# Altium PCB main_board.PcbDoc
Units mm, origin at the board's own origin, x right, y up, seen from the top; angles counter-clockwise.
Board outline 80.25 x 51.3 mm, 2 copper layers (Top Layer, Bottom Layer); 11 components, 14 nets, 56 pads, 87 vias.
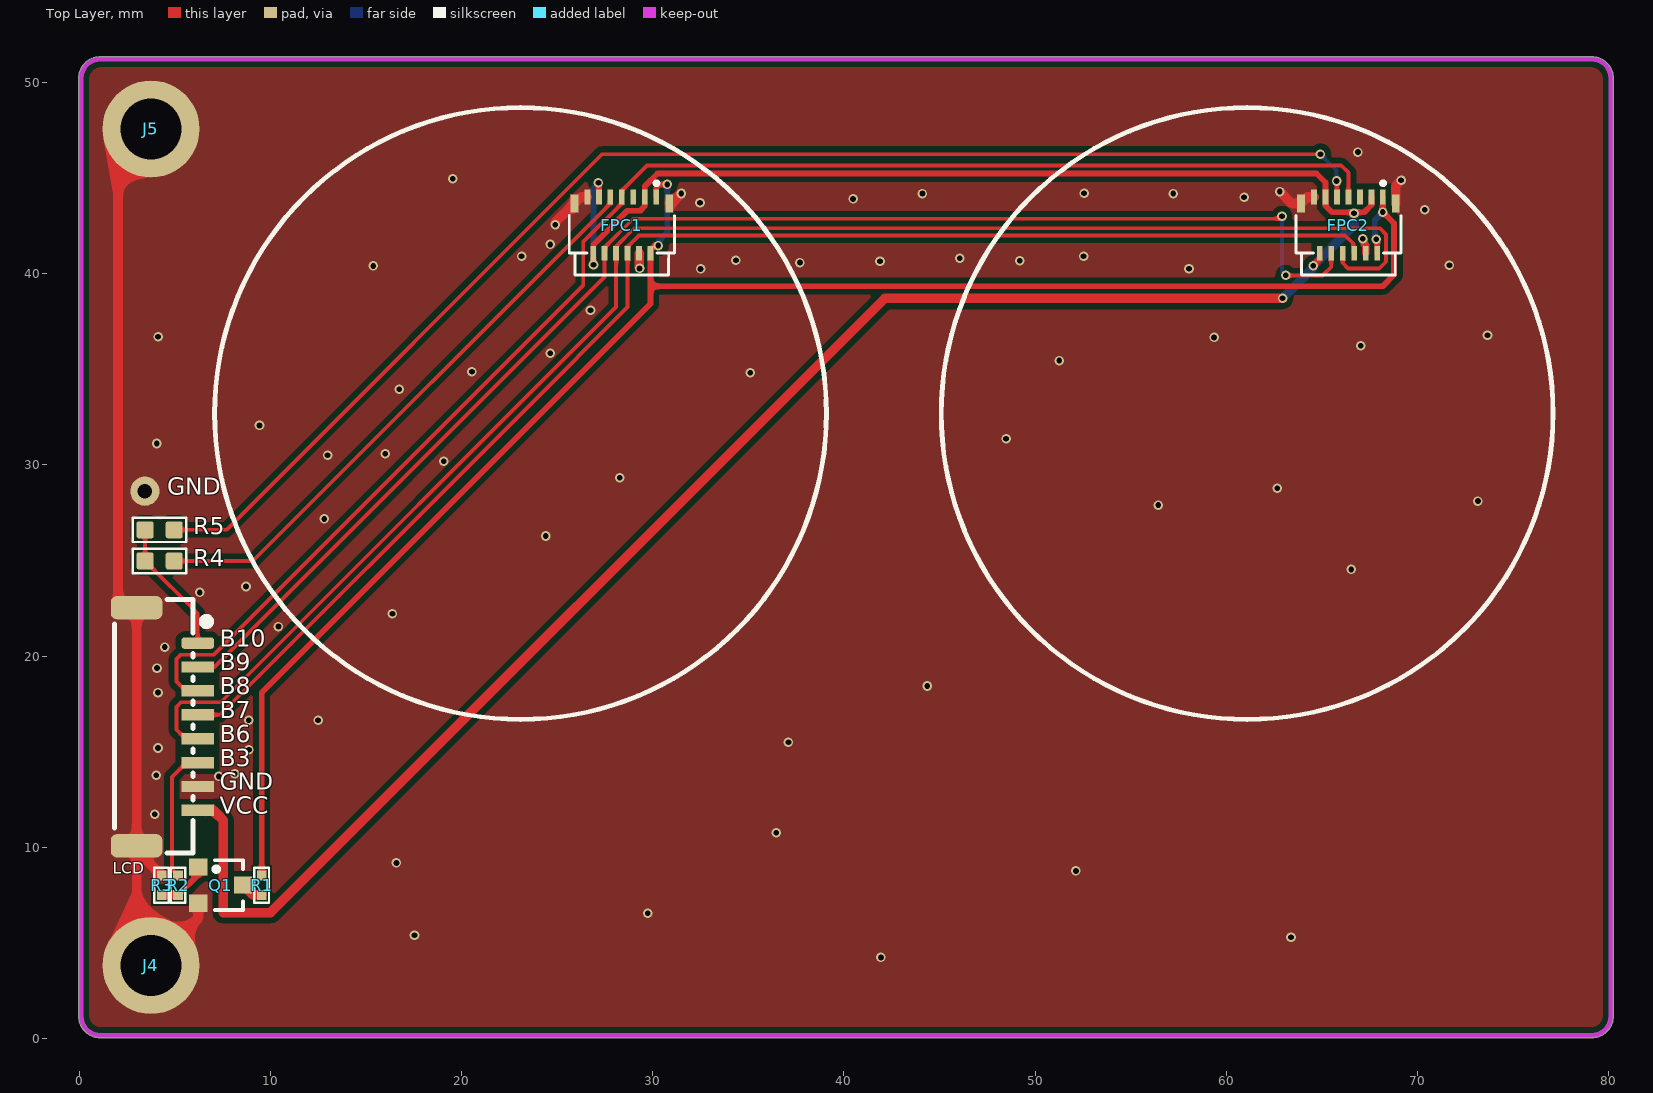
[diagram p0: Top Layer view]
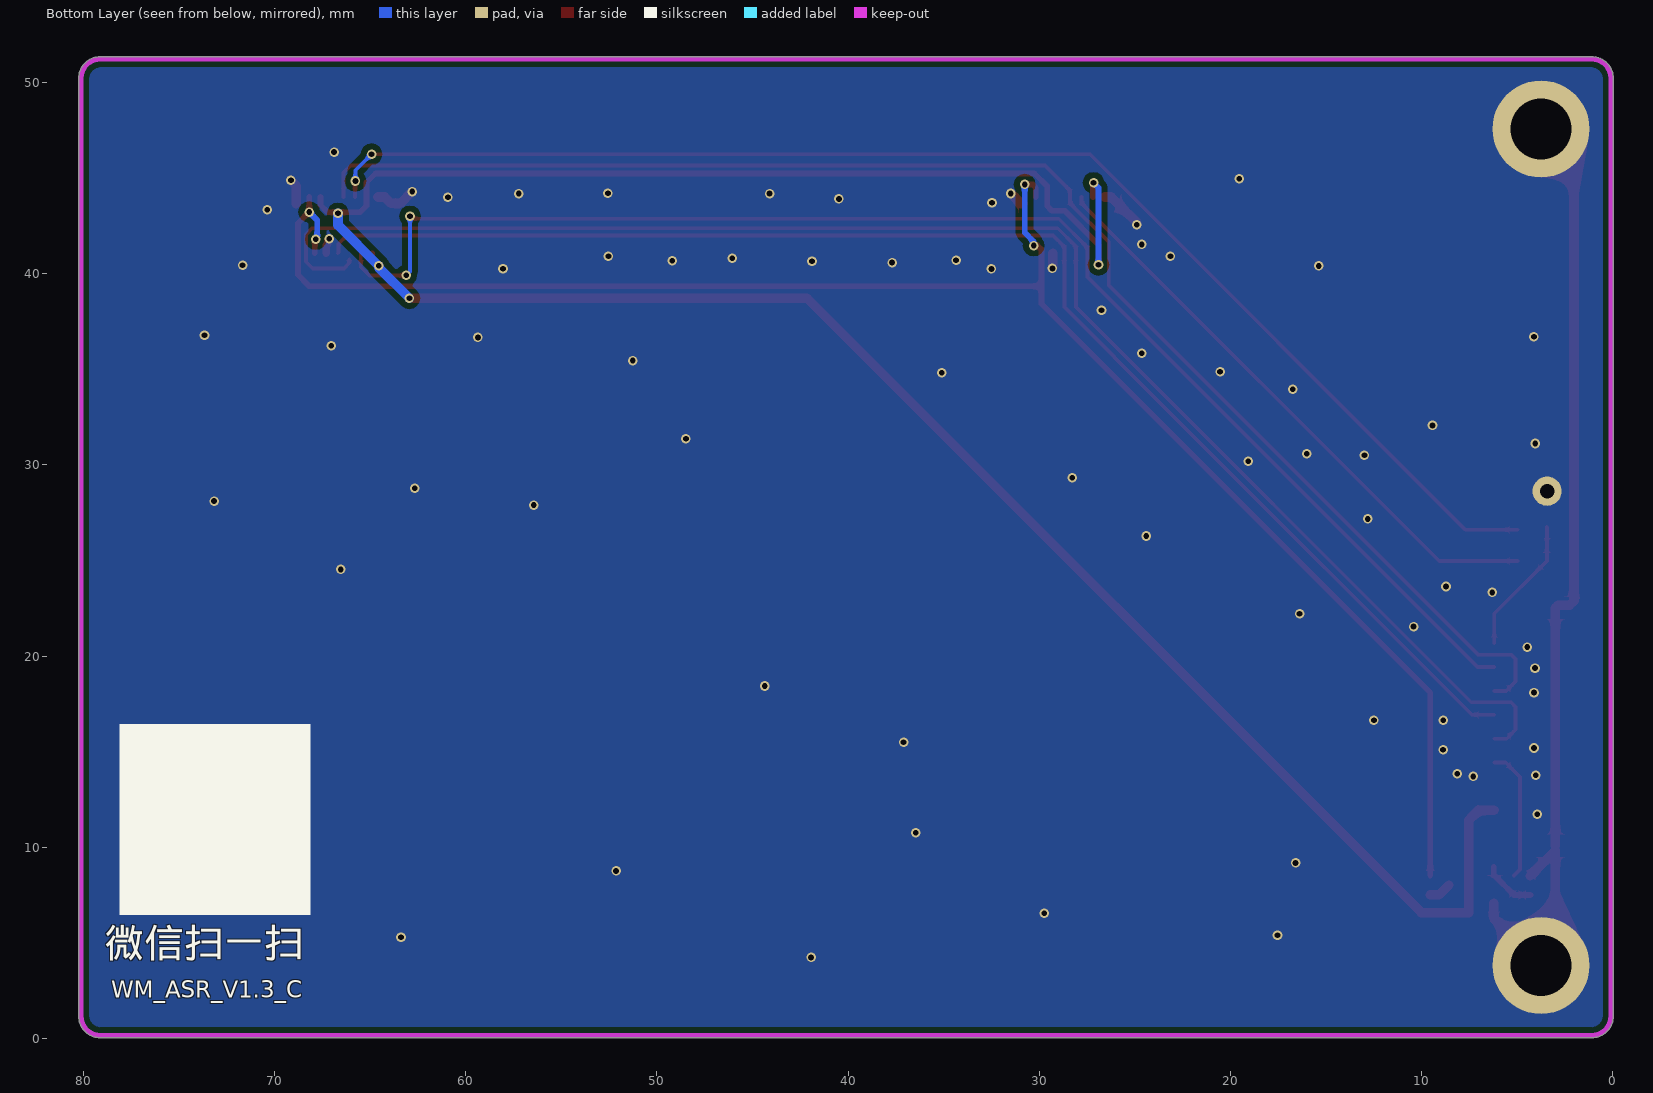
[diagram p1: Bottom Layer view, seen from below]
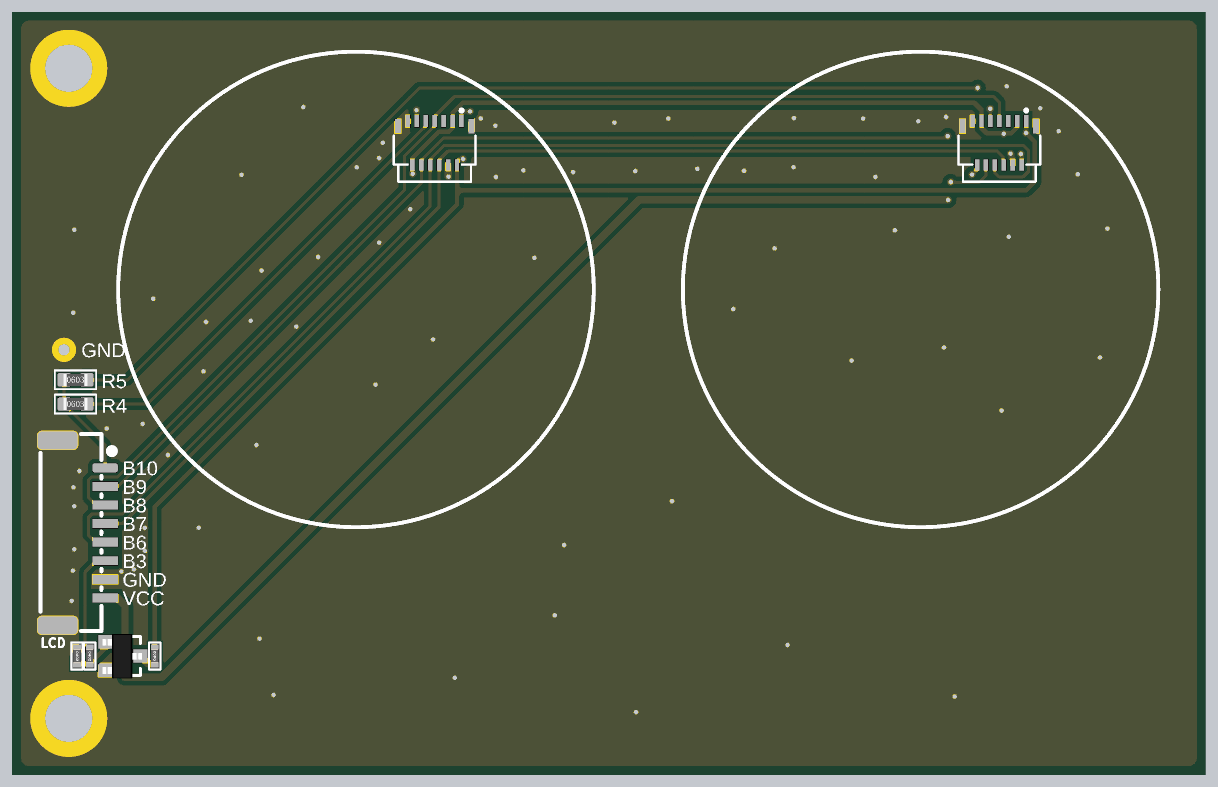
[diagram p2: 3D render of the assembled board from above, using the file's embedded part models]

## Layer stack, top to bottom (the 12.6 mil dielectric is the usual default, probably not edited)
Top Solder: solder mask 0.0102, Solder Resist, Dk 3.5
Top Layer: signal copper 0.0356
Dielectric 1: dielectric 0.32, FR-4, Dk 4.8
Bottom Layer: signal copper 0.0356
Bottom Solder: solder mask 0.0102, Solder Resist, Dk 3.5

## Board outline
-0.016,1.172 -0.016,50.222 cw(c1.111,50.222) 1.027,51.346 cw(c1.055,51.222) 1.055,51.349 79.111,51.349 cw(c79.111,50.222) 80.238,50.222 cw(c80.111,50.222) 80.236,50.196 cw(c80.111,50.169) 80.238,50.169 80.238,1.172 cw(c79.111,1.172) 79.111,0.045 1.111,0.045 cw(c1.111,1.172)

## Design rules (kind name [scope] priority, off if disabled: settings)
Clearance Clearance_freep_ad [HasPad('Free-6') Or HasPad('Free-7') Or HasPad('Free-8') or HasPad('Free-HOLE')] p1: gap=1
Clearance polygon [inpolygon] p2: gap=0.3
Clearance ic [HasFootprint('LQFP48_N') Or HasFootprint('HMC5883L')or HasFootprint('RP4')or HasFootprint('USBMICRO2') Or HasFootprint('JP2_SMD')] p3: gap=0.102
Clearance [All And Not IsKeepOut vs All And Not IsKeepOut] p4: gap=0.17
ComponentClearance [InComponent('J1') vs InComponent('SW1')] p1 off: gap=0 collisioncheckmode=3 verticalgap=2540 showdistances=FALSE
DiffPairsRouting [All] p1: maxlimit=0.254 minlimit=0.2 mostfreqgap=0.2 toplayer_minwidth=0.381 toplayer_maxwidth=0.381 toplayer_prefwidth=0.381 bottomlayer_minwidth=0.381 bottomlayer_maxwidth=0.381 bottomlayer_prefwidth=0.381 maxuncoupledlength=12.7
FabricationTestpoint [(IsPad And (OnTopLayer Or OnBottomLayer))] p1: side=3 testpointundercomponent=TRUE minsize=1.016 maxsize=2.54 preferedsize=1.524 minholesize=0 maxholesize=1.016 preferedholesize=0.813 testpointgrid=0.025 allowsidetop=TRUE allowsidebottom=TRUE usegrid=TRUE gridtolerance=0
HoleSize [All] p1: absolutevalues=TRUE maxlimit=5.08 minlimit=0.152 maxpercent=80.000 minpercent=20.000
MinimumSolderMaskSliver [All] p1: minsoldermaskwidth=0.025
PolygonConnect PolygonConnect_1 [isvia] p1: connectstyle=Direct reliefconductorwidth=0.254 reliefentries=4 polygonreliefangle="90 Angle" airgapwidth=0.254
PolygonConnect [All] p2: connectstyle=Direct reliefconductorwidth=0.254 reliefentries=4 polygonreliefangle="90 Angle" airgapwidth=0.254
RoutingVias [All] p1: holewidth=0.35 width=0.7 viastyle="Through Hole" minholewidth=0.3 minwidth=0.35 maxholewidth=10 maxwidth=10
ShortCircuit [InNet('ANT1') vs InNet('GND')] p1: allowed=TRUE
SilkToSilkClearance [All] p1: silktosilkclearance=0
SilkToSolderMaskClearance SilkscreenOverComponentPads [IsPad] p1 off: minsilkscreentomaskgap=0.051 clearancetoexposedcopper=TRUE
SolderMaskExpansion [All] p1: expansion=0.051
Width Width_1 [InNet('VCC')] p1: maxlimit=25.4 minlimit=0.178 preferedwidth=0.635
Width [All] p2: maxlimit=10 minlimit=0.2 preferedwidth=0.254
22 further rules are at their usual default settings.

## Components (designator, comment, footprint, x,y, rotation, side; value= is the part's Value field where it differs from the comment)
FPC1 "FH35C-13S-0.3SHW(50)" FPC-SMD_13P-P0.60_HRS_FH35C-13S-0.3SHW 23.1,32.7 r0 top locked
FPC2 "FH35C-13S-0.3SHW(50)" FPC-SMD_13P-P0.60_HRS_FH35C-13S-0.3SHW 61.1,32.7 r0 top locked
J4 "M3" "M3 125X200" 3.763,3.823 r0 top locked
J5 "M3" "M3 125X200" 3.763,47.573 r0 top locked
LCD "Header_10" CONN-SMD_SM08B-GHS-TB-LF-SN 4.61,16.308 r270 top locked
Q1 "S8050" SOT-23-3 7.407,8.026 r270 top
R1 "0R" R0402 9.553,8.019 r90 top
R2 "1K" R0402 5.176,8.019 r270 top
R3 "4.7K" R0402 4.318,8.019 r270 top
R4 "0R" R0603 4.216,24.979 r0 top
R5 "0R" R0603 4.216,26.607 r0 top

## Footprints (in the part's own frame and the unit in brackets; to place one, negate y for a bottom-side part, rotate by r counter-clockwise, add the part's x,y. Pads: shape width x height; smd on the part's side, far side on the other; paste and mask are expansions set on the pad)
CONN-SMD_SM08B-GHS-TB-LF-SN [mm]
  rrect50% 0.6x1.7 smd paste+0 mask+0.05: 1(-4.375,1.6)
  rect 0.6x1.7 smd paste+0 mask+0.05: 2(-3.125,1.6) 3(-1.875,1.6) 4(-0.625,1.6) 5(0.625,1.6) 6(1.875,1.6) 7(3.125,1.6) 8(4.375,1.6)
  rrect50% 1.21x2.7 smd paste+0 mask+0.05: 9(-6.225,-1.6) 10(6.225,-1.6)
  silkscreen extent -6.65,-2.75 6.6,2.25
FPC-SMD_13P-P0.60_HRS_FH35C-13S-0.3SHW [mm]
  rect 0.3x0.8 smd: 1(7.088,11.314) 3(6.488,11.314) 5(5.888,11.314) 7(5.288,11.314) 9(4.688,11.314) 11(4.088,11.314) 13(3.488,11.314)
  rect 0.3x0.75 smd: 2(6.788,8.368) 4(6.188,8.368) 6(5.588,8.368) 8(4.988,8.368) 10(4.386,8.369) 12(3.788,8.368)
  rect 0.4x0.95 smd: 14(2.809,10.979) 15(7.767,10.975)
  silkscreen extent -16.01,-16.01 15.99,15.99
"M3 125X200" [mm] "M3螺丝孔，孔125Mil，焊盘200Mil"
  round 5.08 hole 3.175: 1(0,0)
R0402 [mil]
  rect 20x20 smd: 1(-20,0) 2(20,0)
  silkscreen extent -36,-15 36,15, body extent -20,-10 20,10, height 20
R0603 [mil]
  rrect25% 35x35 smd: 1(-30,0) 2(30,0)
  silkscreen extent -55,-25 55,25, body extent -31,-16 32,16, height 18
SOT-23-3 [mm]
  rect 0.9x0.95 smd: 1(-0.95,-1.175) 2(0.95,-1.175) 3(0,1.175)
  silkscreen extent -1.3,-0.35 1.3,1.18, body extent -1.48,-1.37 1.52,1.27, height 1.08

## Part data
FPC1 FPC2: library part FH35C-13S-0.3SHW(50)_C2889266
J4 J5: "铜柱孔"
LCD: library part 180DIP_PH_10
R1: library part R0402/0R
R2: library part R0402/1K
R3: library part R0402/4.7K
R4 R5: library part R0603/0R

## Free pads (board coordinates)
  round 1.524 hole 0.762: 16(3.442,28.628)

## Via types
v1: diameter 0.5, hole 0.3, Top Layer to Bottom Layer, tented both sides, 87 vias

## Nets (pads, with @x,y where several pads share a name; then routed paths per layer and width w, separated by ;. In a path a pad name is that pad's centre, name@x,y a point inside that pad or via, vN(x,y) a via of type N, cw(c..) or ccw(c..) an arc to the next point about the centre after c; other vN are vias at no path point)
3V3: FPC1.3 FPC1.11 FPC1.12 FPC2.3 FPC2.11 FPC2.12 LCD.8 | length 133.1
  Top Layer w0.3: v1(26.907,40.468) 26.888,40.487 FPC1.12 26.888,41.511 28.671,43.294 29.346,43.294 29.588,43.536 FPC1.3 29.588,44.578 30.25,45.24 64.719,45.24 65.188,44.771 FPC2.11 65.188,43.551 65.523,43.216 67.212,43.216 67.588,43.592 FPC2.3 ; v1(27.165,44.757) 27.188,44.734 FPC1.11 ; v1(64.553,40.42) 64.888,40.755 FPC2.12
  Top Layer w0.5: LCD.8 7.029,11.933 7.545,11.417 7.545,6.588 10.023,6.588 42.151,38.716 v1(62.944,38.716)
  Bottom Layer w0.3: v1(26.907,40.468) 26.907,44.499 v1(27.165,44.757)
  Bottom Layer w0.5: v1@62.945,38.716 64.553,40.324 v1(64.553,40.42) 66.68,42.547 v1(66.68,43.162)
B3: LCD.6 R2.1 | length 6.9
  Top Layer w0.2: R2.1 4.865,8.838 4.865,13.688 5.61,14.433 LCD.6
B6: FPC1.8 FPC2.8 LCD.5 | length 82.3
  Top Layer w0.2: LCD.5 5.556,15.683 5.09,16.149 5.09,17.345 5.331,17.586 7.412,17.586 28.088,38.262 FPC1.8 28.088,41.429 29.035,42.376 68.039,42.376 68.357,42.058 68.357,40.629 67.999,40.272 66.368,40.272 66.095,40.545 FPC2.8@66.095,40.755
B7: FPC1.6 FPC2.6 LCD.4 | length 73.4
  Top Layer w0.2: LCD.4 7.369,16.933 22.74,32.304 23.476,33.04 28.688,38.252 FPC1.6 28.688,41.409 29.285,42.006 66.212,42.006 66.646,41.572 66.646,41.111 FPC2.6
B8: FPC1.7 FPC2.7 LCD.3 | length 77.6
  Top Layer w0.2: LCD.3 5.582,18.183 5.09,18.675 5.09,19.845 5.323,20.078 7.05,20.078 26.365,39.393 26.365,41.659 28.388,43.683 FPC1.7 28.388,44.346 29.703,45.66 66.014,45.66 66.388,45.286 FPC2.7
B9: FPC1.10 FPC2.10 LCD.2 | length 73.8
  Top Layer w0.2: LCD.2 7.084,19.433 27.486,39.835 FPC1.10 27.486,41.373 28.987,42.874 62.783,42.874 62.914,43.005 v1(62.914,43.008) ; v1(63.116,39.921) 63.137,39.9 65.034,39.9 65.486,40.352 FPC2.10
  Bottom Layer w0.2: v1(62.914,43.008) 62.914,40.123 v1(63.116,39.921)
B10: LCD.1 R4.1 R5.1 | length 7.2
  Top Layer w0.2: R5.1@3.464,26.751 3.454,26.741 R5.1 R4.1 6.21,22.223 LCD.1
CS1: FPC1.9 R4.2 | length 30.9
  Top Layer w0.2: R4.2 9.085,24.979 27.788,43.682 FPC1.9
CS2: FPC2.9 R5.2 | length 70.7
  Top Layer w0.2: R5.2 7.703,26.607 27.349,46.253 v1(64.924,46.253) ; v1(65.768,44.851) 65.788,44.831 FPC2.9
  Bottom Layer w0.2: v1(64.924,46.253) 65.768,45.409 v1(65.768,44.851)
GND: FPC1.4 FPC1.13 FPC1.14 FPC1.15 FPC2.4 FPC2.13 FPC2.14 FPC2.15 J4.1 J5.1 LCD.7 LCD.9 LCD.10 pad.16 Q1.2 R3.1 | length 59.7
  Top Layer w0.4: v1(67.142,41.827) 67.217,41.752 67.217,41.548 67.288,41.476 FPC2.4
  Top Layer w0.5: LCD.10 LCD.9 2.877,22.666 2.263,22.666 2.036,22.893 2.036,45.846 J5.1 ; R3.1 3.01,9.835 3.01,4.576 J4.1 6.232,6.292 Q1.2 ; v1(24.9,42.567) 24.9,42.67 FPC1.14 26.244,44.014 FPC1.13 ; FPC1.4 29.288,40.306 v1(29.314,40.28) ; FPC1.15 30.966,43.675 v1(31.488,44.197) ; v1(62.801,44.297) 63.419,43.679 FPC2.14 64.244,44.014 FPC2.13 ; FPC2.15 68.867,44.612 v1(69.143,44.888)
  other v1: 41.936,4.246 63.383,5.297 17.545,5.402 29.741,6.559 52.134,8.767 16.599,9.187 36.469,10.764 3.954,11.732 7.302,13.711 4.042,13.769 8.146,13.847 8.884,15.099 4.129,15.196 37.1,15.495 8.874,16.642 12.499,16.652 4.129,18.097 44.354,18.439 4.077,19.375 4.478,20.474 10.429,21.549 16.389,22.224 6.319,23.331 8.732,23.643 66.537,24.537 24.407,26.283 12.829,27.179 56.445,27.901 73.161,28.111 62.662,28.784 28.281,29.324 19.071,30.191 12.996,30.507 16.012,30.59 4.059,31.123 48.484,31.37 9.439,32.067 16.74,33.959 35.099,34.817 20.546,34.875 51.262,35.457 24.649,35.844 67.026,36.235 59.361,36.67 4.135,36.705 73.661,36.784 26.748,38.095 32.505,40.252 58.05,40.264 15.388,40.407 71.671,40.445 37.703,40.583 41.888,40.657 34.352,40.7 49.204,40.68 46.063,40.805 23.144,40.91 52.538,40.919 24.648,41.533 70.378,43.344 32.475,43.707 40.483,43.914 60.93,44.006 44.107,44.191 57.22,44.191 52.564,44.216 19.548,44.963 66.885,46.361
LEDK: FPC1.1 FPC1.2 FPC2.1 FPC2.2 R1.2 | length 92
  Top Layer w0.3: R1.2 9.553,18.093 29.888,38.428 29.888,39.351 ; FPC1.1 30.188,44.513 30.345,44.67 v1(30.767,44.67) ; v1(30.298,41.471) 30.088,41.471 29.888,41.271 FPC1.2 29.888,39.351 ; v1(67.837,41.805) 67.888,41.753 FPC2.2 ; FPC2.1 v1(68.188,43.226) 68.777,42.637 68.777,39.95 68.178,39.351 29.888,39.351
  Bottom Layer w0.3: v1(30.298,41.471) 30.298,41.681 30.767,42.15 v1(30.767,44.67) ; v1(67.837,41.805) 67.761,41.88 67.761,42.799 v1(68.188,43.226)
NetQ1_1: Q1.1 R2.2 R3.2 | length 2.8
  Top Layer w0.3: R3.2 R2.2 6.232,8.567 Q1.1
NetQ1_3: Q1.3 R1.1 | length 1.2
  Top Layer w0.5: Q1.3 9.097,7.511 R1.1
TE: FPC2.5
pads on no net: FPC1.5

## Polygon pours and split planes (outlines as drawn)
GND on Top Layer "Top Layer-No Net" (solid, remove dead copper, pour order 0): -7.314,59.46 86.786,59.46 86.786,-0.26 -7.217,-0.26
GND on Bottom Layer "Top Layer-No Net" (solid, remove dead copper, pour order 4): -7.323,55.371 86.777,55.371 86.777,-4.349 -7.226,-4.349

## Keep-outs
Keep-Out Layer:
  lines w0.254: 1.055,51.222 79.111,51.222 cw(c79.111,50.222) 80.111,50.222 ; 1.111,51.222 ccw(c1.111,50.222) 0.111,50.222 0.111,1.172 ccw(c1.111,1.172) 1.111,0.172 79.111,0.172 ccw(c79.111,1.172) 80.111,1.172 80.111,50.169

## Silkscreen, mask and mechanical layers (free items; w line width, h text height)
Top Overlay:
  text "GND" at 4.604,28.135 h1.52
  text "B10" at 7.372,20.19 h1.52
  text "B9" at 7.372,18.94 h1.52
  text "B8" at 7.372,17.69 h1.52
  text "B7" at 7.372,16.44 h1.52
  text "B6" at 7.372,15.19 h1.52
  text "B3" at 7.372,13.94 h1.52
  text "GND" at 7.372,12.69 h1.52
  text "VCC" at 7.372,11.44 h1.52
Bottom Overlay:
  region: 68.117,16.464 68.117,6.464 78.117,6.464 78.117,16.464
  text "微信扫一扫" at 78.903,3.748 h2.6
  text "WM_ASR_V1.3_C" at 78.547,1.856 h1.5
